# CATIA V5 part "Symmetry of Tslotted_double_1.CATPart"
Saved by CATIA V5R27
Part number: Symmetry of Tslotted_double_1
Bounding box of the stored display mesh (mm): x -19.05 to 19.05, y -19.05 to 19.05, z -381 to 381
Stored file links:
  \\triton.meca.polymtl.ca\usagers\zaoue\profiles\Desktop\varm_ass\structure prismatique\Symmetry of Tslotted_double_1.CATPart
  \\triton.meca.polymtl.ca\usagers\zaoue\profiles\Desktop\varm_ass\structure prismatique\Alu_Tslot_double.CATPart
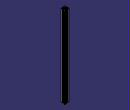
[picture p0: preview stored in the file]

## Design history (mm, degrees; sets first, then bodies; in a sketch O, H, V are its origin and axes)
Body1 (main body)
  Body2 "Corps du corps principal d'origine"
    Solid1: linked copy from another document
  Assemble1: tool Body2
